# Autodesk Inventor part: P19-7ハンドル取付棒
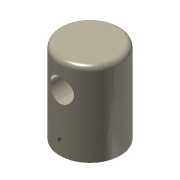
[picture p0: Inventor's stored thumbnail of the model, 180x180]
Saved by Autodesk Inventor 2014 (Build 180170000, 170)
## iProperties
Created: 2008-07
Part Number: P19-7ハンドル取付棒
Document SubType Name: Modeling
Designer: y-shimohigashi
Density: 1 g/cm^3
Stock Number: P19-7ハンドル取付棒
Material: 一般
Appearance: 淡いベージュ
Author: y-shimohigashi
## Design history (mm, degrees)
sketch "スケッチ1"
  geometry: C1 r 18 at (0, 0); 1 further point
  constraints: 1 centre point, 1 coincident
  dimensions: "d0" = 36 diameter of C1
extrude "押し出し1" new body sketch "スケッチ1" distance "d1" = 50; taper "d2" = 0 deg
sketch "スケッチ2"
  geometry: L1 (0, -10)-(0, 60) reference; L2 (-18, 50)-(18, 50) reference; C1 r 7 at (0, 34)
  constraints: 1 centre point, 1 point on line
  dimensions: "d3" = 14 diameter of C1; "d4" = 16 distance from line of L2 C1.centre
extrude "押し出し2" cut sketch "スケッチ2" stored distance "d5" = 50; taper "d6" = 0 deg
sketch "スケッチ3"
  geometry: L1 (0, -10)-(0, 60) reference; L2 (-18, 0)-(18, 0) reference; C1 r 1.5 at (0, 8)
  constraints: 1 centre point, 1 point on line
  dimensions: "d7" = 3 diameter of C1; "d8" = 8 distance from line of L2 C1.centre
extrude "押し出し3" cut sketch "スケッチ3" stored distance "d9" = 50; taper "d10" = 0 deg
feature "ねじ1" dims "d11" = 10, "d12" = 0
fillet "フィレット1" dims "d13" = 3
sketch "スケッチ4"
  geometry: L1 (3.536, -3.536)-(-3.536, -3.536); L2 (-3.536, -3.536)-(-3.536, 3.536); L3 (-3.536, 3.536)-(3.536, 3.536); L4 (3.536, 3.536)-(3.536, -3.536); L5 (3.536, 3.536)-(-3.536, -3.536); 2 further points
  constraints: 10 end point, 2 parallel, 2 perpendicular, 1 coincident, 1 horizontal, 1 midpoint
  dimensions: "d14" = 10 distance of L3.end L1.end
extrude "押し出し4" cut sketch "スケッチ4" stored distance "d15" = 50; taper "d16" = 0 deg
node "ソリッド1"
node "ソリッド ボディ"
node "サーフェス ボディ"
